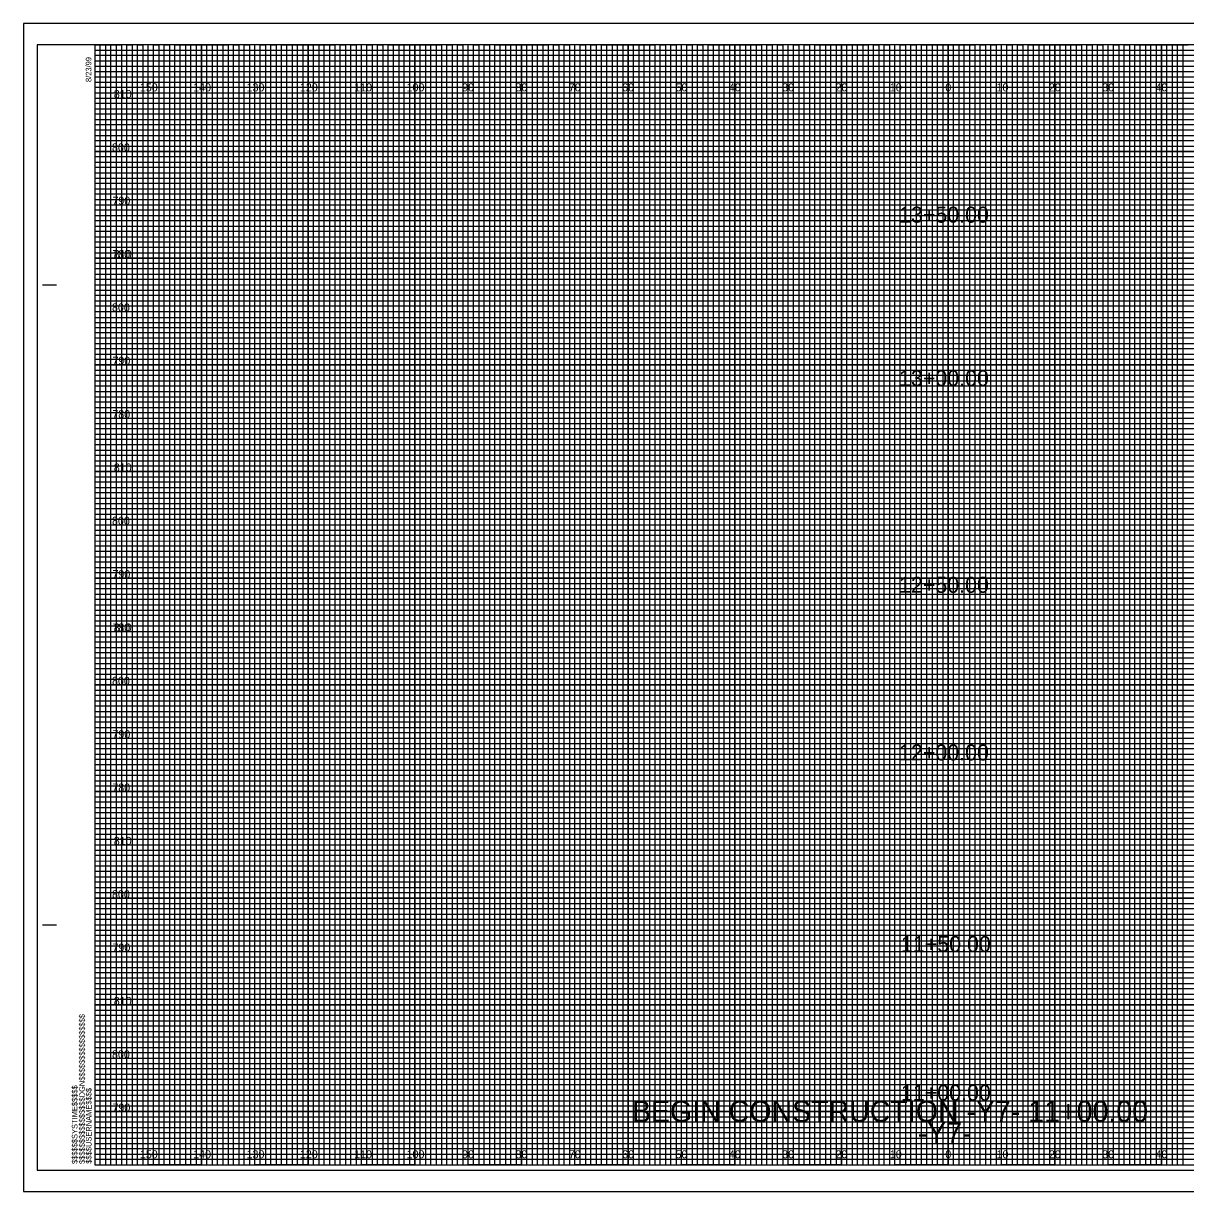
# Model space of a CAD drawing. Extents: x -13 to 323, y -5 to 214.
# Drawn here: x -13.4 to 204.5, y -5 to 214 of the extents above; entities that cross this region are included whole.
import ezdxf

# ---------------------------------------------------------------- set-up
doc = ezdxf.new("R2010")
doc.units = 0
for name, color, linetype in [('Prop XS Alignment Label', 7, 'Continuous'), ('Prop XS Elevation Labels', 7, 'Continuous'), ('Prop XS Offset Labels', 7, 'Continuous'), ('Prop XS Station Labels', 7, 'Continuous'), ('Sheet Cross Section CELL', 7, 'Continuous'), ('Sheet Cross Section Grid Major CELL', 7, 'Continuous'), ('Sheet Cross Section Grid Middle CELL', 7, 'Continuous'), ('Sheet Cross Section Grid Minor 1 CELL', 7, 'Continuous'), ('Sheet Cross Section Grid Minor 2 CELL', 7, 'Continuous'), ('Sheet Cutting Line CELL', 7, 'Continuous'), ('Sheet DOT Grid CELL', 7, 'Continuous'), ('Sheet Plot Border Inside CELL', 7, 'Continuous'), ('Sheet Plot Border Outside CELL', 7, 'Continuous')]:
    doc.layers.add(name, color=color, linetype=linetype)

msp = doc.modelspace()

# ---------------------------------------------------------------- linework, layer by layer
at = {"layer": 'Sheet Cross Section CELL'}
for p, q in [((-9.8, 165), (-7.3, 165)), ((-9.7, 165), (-7.2, 165)), ((-9.8, 45), (-7.3, 45)), ((-9.7, 45), (-7.2, 45)), ((0, 0), (0, 0)), ((0, 0), (0, 0)), ((0, 0), (0, 0)), ((0, 0), (0, 0)), ((0, 0), (0, 0)), ((0, 0), (0, 0)), ((0, 0), (0, 0))]:
    msp.add_line(p, q, dxfattribs=at)
msp.add_lwpolyline([(320, 210), (0, 210), (0, 0), (320, 0)], close=True, dxfattribs=at)
at = {"layer": 'Sheet Cross Section Grid Major CELL'}
for p, q in [((10, 210), (0, 210)), ((10, 0), (10, 210)), ((30, 210), (20, 210)), ((20, 210), (20, 0)), ((30, 0), (30, 210)), ((50, 210), (40, 210)), ((40, 210), (40, 0)), ((50, 0), (50, 210)), ((70, 210), (60, 210)), ((60, 210), (60, 0)), ((70, 0), (70, 210)), ((90, 210), (80, 210)), ((80, 210), (80, 0)), ((90, 0), (90, 210)), ((110, 210), (100, 210)), ((100, 210), (100, 0)), ((110, 0), (110, 210)), ((130, 210), (120, 210)), ((120, 210), (120, 0)), ((130, 0), (130, 210)), ((150, 210), (140, 210)), ((140, 210), (140, 0)), ((150, 0), (150, 210)), ((170, 210), (160, 210)), ((160, 210), (160, 0)), ((170, 0), (170, 210)), ((190, 210), (180, 210)), ((180, 210), (180, 0)), ((190, 0), (190, 210)), ((210, 210), (200, 210)), ((200, 210), (200, 0)), ((20, 0), (10, 0)), ((40, 0), (30, 0)), ((60, 0), (50, 0)), ((80, 0), (70, 0)), ((100, 0), (90, 0)), ((120, 0), (110, 0)), ((140, 0), (130, 0)), ((160, 0), (150, 0)), ((180, 0), (170, 0)), ((200, 0), (190, 0))]:
    msp.add_line(p, q, dxfattribs=at)
for points in [[(0, 200), (320, 200), (320, 190), (0, 190)], [(0, 180), (320, 180), (320, 170), (0, 170)], [(0, 160), (320, 160), (320, 150), (0, 150)], [(0, 140), (320, 140), (320, 130), (0, 130)], [(0, 120), (320, 120), (320, 110), (0, 110)], [(0, 100), (320, 100), (320, 90), (0, 90)], [(0, 80), (320, 80), (320, 70), (0, 70)], [(0, 60), (320, 60), (320, 50), (0, 50)], [(0, 40), (320, 40), (320, 30), (0, 30)], [(0, 20), (320, 20), (320, 10), (0, 10)]]:
    msp.add_lwpolyline(points, dxfattribs=at)
at = {"layer": 'Sheet Cross Section Grid Middle CELL'}
for points in [[(0, 210), (5, 210), (5, 0), (15, 0), (15, 210), (25, 210), (25, 0), (35, 0), (35, 210), (45, 210), (45, 0), (55, 0), (55, 210), (65, 210), (65, 0), (75, 0), (75, 210), (85, 210), (85, 0), (95, 0), (95, 210), (105, 210), (105, 0), (115, 0), (115, 210), (125, 210), (125, 0), (135, 0), (135, 210), (145, 210), (145, 0), (155, 0), (155, 210), (165, 210), (165, 0), (175, 0), (175, 210), (185, 210), (185, 0), (195, 0), (195, 210), (205, 210)], [(0, 205), (275, 205)], [(0, 185), (320, 185), (320, 195), (0, 195)], [(0, 165), (320, 165), (320, 175), (0, 175)], [(0, 145), (320, 145), (320, 155), (0, 155)], [(0, 125), (320, 125), (320, 135), (0, 135)], [(0, 105), (320, 105), (320, 115), (0, 115)], [(0, 85), (320, 85), (320, 95), (0, 95)], [(0, 65), (320, 65), (320, 75), (0, 75)], [(0, 45), (320, 45), (320, 55), (0, 55)], [(0, 25), (320, 25), (320, 35), (0, 35)], [(0, 5), (320, 5), (320, 15), (0, 15)]]:
    msp.add_lwpolyline(points, dxfattribs=at)
at = {"layer": 'Sheet Cross Section Grid Minor 1 CELL'}
for p, q in [((0, 209), (260, 209)), ((260, 207.98), (0, 207.98)), ((0, 207.98), (0, 207)), ((0, 207), (260, 207)), ((260, 205.89), (0, 205.89)), ((0, 205.89), (0, 204)), ((0, 204), (320, 204))]:
    msp.add_line(p, q, dxfattribs=at)
for points in [[(0, 203), (270, 203), (320, 203), (320, 202), (0, 202)], [(0, 201), (320, 201), (320, 199), (0, 199)], [(0, 198), (320, 198), (320, 197), (0, 196.98)], [(0, 196), (320, 196), (320, 194), (0, 194)], [(0, 193), (320, 193), (320, 192), (0, 192)], [(0, 191), (320, 191), (320, 189), (0, 189)], [(0, 188), (320, 188), (320, 187), (0, 187)], [(0, 186), (320, 186), (320, 184), (0, 184)], [(0, 183), (320, 183), (320, 182), (0, 182)], [(0, 181), (320, 181), (320, 179), (0, 179)], [(0, 178), (320, 178), (320, 177), (0, 177)], [(0, 176), (320, 176), (320, 173.95), (320, 173), (320, 172), (0, 172)], [(0, 174), (320, 174), (320, 173), (0, 173)], [(0, 171), (320, 171), (320, 169), (0, 169.03)], [(0, 169.03), (320, 169), (320, 168), (0, 168)], [(0, 167), (320, 167), (320, 166), (0, 166)], [(0, 164), (320, 164), (320, 163), (0, 163)], [(0, 162), (320, 162), (320, 161), (0, 161)], [(-0.07, 158.89), (320, 158.89), (320, 157.88), (-0.07, 157.88)], [(0, 157), (320, 157), (320, 156), (0, 156)], [(0, 154), (320, 154), (320, 153), (0, 153)], [(0, 152), (320, 152), (320, 151), (0, 151)], [(0, 149), (320, 149), (320, 148), (0, 148)], [(0, 147), (320, 147), (320, 146), (0, 146)], [(0, 144), (320, 144), (320, 143), (0, 143)], [(0, 142), (320, 142), (320, 141), (0, 141)], [(0, 139), (320, 139), (319.99, 137.98), (0, 138)], [(0, 137), (320, 137), (320, 136), (0, 136)], [(0, 134), (320, 134), (320, 133), (0, 133)], [(0, 132), (320, 132), (320, 131), (0, 131)], [(0, 129), (320, 129), (320, 128), (0, 128)], [(0, 127), (320, 127), (320, 126), (0, 126)], [(0, 124), (320, 124), (320, 123), (0, 123)], [(0, 122), (320, 122), (320, 121), (0, 121)], [(0, 119), (320, 119), (320, 118), (0, 118)], [(0, 116.99), (320.07, 116.91), (320, 116), (0, 116)], [(0, 114), (320, 114), (320, 113), (0, 113)], [(0, 112), (320, 112), (320, 111), (0, 111)], [(0, 109), (320, 109), (320, 108), (0, 108)], [(0, 107), (320, 107), (320, 106), (0, 106)], [(0, 104), (320, 104), (320, 103), (0, 103)], [(0, 102), (320, 102), (320, 101), (0, 101)], [(0, 99), (320, 99), (320, 98), (0, 98)], [(0, 97), (320, 97), (320, 96), (0, 96)], [(0, 94), (320, 94), (320, 93), (0, 93)], [(0, 92), (320, 92), (320, 91), (0, 91)], [(0, 89), (320, 89), (320, 88), (0, 88)], [(0, 87), (320, 87), (320, 86), (0, 86)], [(0, 84), (320, 84), (320, 83), (0, 83)], [(0, 82), (320, 82), (320, 81), (0, 81)], [(0, 79), (320, 79), (319.99, 77.98), (0, 78)], [(0, 77), (320, 77), (320, 76), (0, 76)], [(0, 74), (320, 74), (320, 73), (0, 73)], [(0, 72), (320, 72), (320, 71), (0, 71)], [(0, 69), (320, 69), (320, 68), (0, 68)], [(0, 67), (320, 67), (320, 66), (0, 66)], [(0, 64), (320, 64), (320, 63), (0, 63)], [(0, 62), (320, 62), (320, 61), (0, 61)], [(0, 59), (320, 59), (320, 58), (0, 58)], [(0, 56.99), (320.07, 56.91), (320, 56), (0, 56)], [(0, 54), (320, 54), (320, 53), (0, 53)], [(0, 52), (320, 52), (320, 51), (0, 51)], [(0, 49), (320, 49), (320, 48), (0, 48)], [(0, 47), (320, 47), (320, 46), (0, 46)], [(0, 44), (320, 44), (320, 43), (0, 43)], [(0, 42), (320, 42), (320, 41), (0, 41)], [(0, 39), (320, 39), (320, 38), (0, 38)], [(0, 37), (320, 37), (320, 36), (0, 36)], [(0, 34), (320, 34), (320, 33), (0, 33)], [(0, 32), (320, 32), (320, 31), (0, 31)], [(0, 29), (320, 29), (320, 28), (0, 28)], [(0, 27), (320, 27), (320, 26), (0, 26)], [(0, 24), (320, 24), (320, 23), (0, 23)], [(0, 22), (320, 22), (320, 21), (0, 21)], [(0, 19), (320, 19), (320, 18), (0, 18)], [(0, 17), (320, 17), (320, 16), (0, 16)], [(0, 14), (320, 14), (320, 13), (0, 13)], [(0, 12), (320, 12), (320, 11), (0, 11)], [(0, 9), (320, 9), (320, 8), (0, 8)], [(0, 7), (320, 7), (320, 6), (0, 6)], [(0, 4), (320, 4), (320, 3), (0, 3)], [(0, 2), (320, 2), (320, 1), (0, 1)]]:
    msp.add_lwpolyline(points, dxfattribs=at)
at = {"layer": 'Sheet Cross Section Grid Minor 2 CELL'}
for points in [[(0, 0), (1, 0), (1, 210), (2, 210), (2, 0)], [(2, 0), (3, 0), (3, 210), (4, 210), (4, 0)], [(5, 0), (6, 0), (6, 210), (7, 210), (7, 0)], [(7, 0), (8, 0), (8, 210), (9, 210), (9, 0)], [(10, 0), (11, 0), (11, 210), (12, 210), (12, 0)], [(12, 0), (13, 0), (13, 210), (14, 210), (14, 0)], [(15, 0), (16, 0), (16, 210), (17, 210), (17, 0)], [(17, 0), (18, 0), (18, 210), (19, 210), (19, 0)], [(20, 0), (21, 0), (21, 210), (22, 210), (22, 0)], [(22, 0), (23, 0), (23, 210), (24, 210), (24, 0)], [(25, 0), (26, 0), (26, 210), (27, 210), (27, 0)], [(27, 0), (28, 0), (28, 210), (29, 210), (29, 0)], [(30, 0), (31, 0), (31, 210), (32, 210), (32, 0)], [(32, 0), (33, 0), (33, 210), (34, 210), (34, 0)], [(35, 0), (36, 0), (36, 210), (37, 210), (37, 0)], [(37, 0), (38, 0), (38, 210), (39, 210), (39, 0)], [(40, 0), (41, 0), (41, 210), (42, 210), (42, 0)], [(42, 0), (43, 0), (43, 210), (44, 210), (44, 0)], [(45, 0), (46, 0), (46, 210), (47, 210), (47, 0)], [(47, 0), (48, 0), (48, 210), (49, 210), (49, 0)], [(50, 0), (51, 0), (51, 210), (52, 210), (52, 0)], [(52, 0), (53, 0), (53, 210), (54, 210), (54, 0)], [(55, 0), (56, 0), (56, 210), (57, 210), (57, 0)], [(57, 0), (58, 0), (58, 210), (59, 210), (59, 0)], [(60, 0), (61, 0), (61, 210), (62, 210), (62, 0)], [(62, 0), (63, 0), (63, 210), (64, 210), (64, 0)], [(65, 0), (66, 0), (66, 210), (67, 210), (67, 0)], [(67, 0), (68, 0), (68, 210), (69, 210), (69, 0)], [(70, 0), (71, 0), (71, 210), (72, 210), (72, 0)], [(72, 0), (73, 0), (73, 210), (74, 210), (74, 0)], [(75, 0), (76, 0), (76, 210), (77, 210), (77, 0)], [(77, 0), (78, 0), (78, 210), (79, 210), (79, 0)], [(80, 0), (81, 0), (81, 210), (82, 210), (82, 0)], [(82, 0), (83, 0), (83, 210), (84, 210), (84, 0)], [(85, 0), (86, 0), (86, 210), (87, 210), (87, 0)], [(87, 0), (88, 0), (88, 210), (89, 210), (89, 0)], [(90, 0), (91, 0), (91, 210), (92, 210), (92, 0)], [(92, 0), (93, 0), (93, 210), (94, 210), (94, 0)], [(95, 0), (96, 0), (96, 210), (97, 210), (97, 0)], [(97, 0), (98, 0), (98, 210), (99, 210), (99, 0)], [(100, 0), (101, 0), (101, 210), (102, 210), (102, 0)], [(102, 0), (103, 0), (103, 210), (104, 210), (104, 0)], [(105, 0), (106, 0), (106, 210), (107, 210), (107, 0)], [(107, 0), (108, 0), (108, 210), (109, 210), (109, 0)], [(110, 0), (111, 0), (111, 210), (112, 210), (112, 0)], [(112, 0), (113, 0), (113, 210), (114, 210), (114, 0)], [(115, 0), (116, 0), (116, 210), (117, 210), (117, 0)], [(117, 0), (118, 0), (118, 210), (119, 210), (119, 0)], [(120, 0), (121, 0), (121, 210), (122, 210), (122, 0)], [(122, 0), (123, 0), (123, 210), (124, 210), (124, 0)], [(125, 0), (126, 0), (126, 210), (127, 210), (127, 0)], [(127, 0), (128, 0), (128, 210), (129, 210), (129, 0)], [(130, 0), (131, 0), (131, 210), (132, 210), (132, 0)], [(132, 0), (133, 0), (133, 210), (134, 210), (134, 0)], [(135, 0), (136, 0), (136, 210), (137, 210), (137, 0)], [(137, 0), (138, 0), (138, 210), (139, 210), (139, 0)], [(140, 0), (141, 0), (141, 210), (142, 210), (142, 0)], [(142, 0), (143, 0), (143, 210), (144, 210), (144, 0)], [(145, 0), (146, 0), (146, 210), (147, 210), (147, 0)], [(147, 0), (148, 0), (148, 210), (149, 210), (149, 0)], [(150, 0), (151, 0), (151, 210), (152, 210), (152, 0)], [(152, 0), (153, 0), (153, 210), (154, 210), (154, 0)], [(155, 0), (156, 0), (156, 210), (157, 210), (157, 0)], [(157, 0), (158, 0), (158, 210), (159, 210), (159, 0)], [(160, 0), (161, 0), (161, 210), (162, 210), (162, 0)], [(162, 0), (163, 0), (163, 210), (164, 210), (164, 0)], [(165, 0), (166, 0), (166, 210), (167, 210), (167, 0)], [(167, 0), (168, 0), (168, 210), (169, 210), (169, 0)], [(170, 0), (171, 0), (171, 210), (172, 210), (172, 0)], [(172, 0), (173, 0), (173, 210), (174, 210), (174, 0)], [(175, 0), (176, 0), (176, 210), (177, 210), (177, 0)], [(177, 0), (178, 0), (178, 210), (179, 210), (179, 0)], [(180, 0), (181, 0), (181, 210), (182, 210), (182, 0)], [(182, 0), (183, 0), (183, 210), (184, 210), (184, 0)], [(185, 0), (186, 0), (186, 210), (187, 210), (187, 0)], [(187, 0), (188, 0), (188, 210), (189, 210), (189, 0)], [(190, 0), (191, 0), (191, 210), (192, 210), (192, 0)], [(192, 0), (193, 0), (193, 210), (194, 210), (194, 0)], [(195, 0), (196, 0), (196, 210), (197, 210), (197, 0)], [(197, 0), (198, 0), (198, 210), (199, 210), (199, 0)], [(200, 0), (201, 0), (201, 210), (202, 210), (202, 0)], [(202, 0), (203, 0), (203, 210), (204, 210), (204, 0)]]:
    msp.add_lwpolyline(points, dxfattribs=at)
at = {"layer": 'Sheet Cutting Line CELL'}
for p, q in [((323.3, 214), (-13.4, 214)), ((-13.4, 214), (-13.4, -5)), ((-13.4, -5), (323.3, -5))]:
    msp.add_line(p, q, dxfattribs=at)
at = {"layer": 'Sheet DOT Grid CELL'}
for p, q in [((10, 0), (10, 210)), ((20, 0), (20, 210)), ((30, 0), (30, 210)), ((40, 0), (40, 210)), ((50, 0), (50, 210)), ((60, 0), (60, 210)), ((70, 0), (70, 210)), ((80, 0), (80, 210)), ((90, 0), (90, 210)), ((100, 0), (100, 210)), ((110, 0), (110, 210)), ((120, 0), (120, 210)), ((130, 0), (130, 210)), ((140, 0), (140, 210)), ((150, 0), (150, 210)), ((160, 0), (160, 210)), ((170, 0), (170, 210)), ((180, 0), (180, 210)), ((190, 0), (190, 210)), ((200, 0), (200, 210)), ((0, 200), (320, 200)), ((0, 190), (320, 190)), ((0, 180), (320, 180)), ((0, 170), (320, 170)), ((0, 160), (320, 160)), ((0, 150), (320, 150)), ((0, 140), (320, 140)), ((0, 130), (320, 130)), ((0, 120), (320, 120)), ((0, 110), (320, 110)), ((0, 100), (320, 100)), ((0, 90), (320, 90)), ((0, 80), (320, 80)), ((0, 70), (320, 70)), ((0, 60), (320, 60)), ((0, 50), (320, 50)), ((0, 40), (320, 40)), ((0, 30), (320, 30)), ((0, 20), (320, 20)), ((0, 10), (320, 10))]:
    msp.add_line(p, q, dxfattribs=at)
at = {"layer": 'Sheet Plot Border Inside CELL'}
msp.add_lwpolyline([(-10.8, -1), (322.4, -1), (322.4, 210), (-10.8, 210)], close=True, dxfattribs=at)
at = {"layer": 'Sheet Plot Border Outside CELL'}
msp.add_lwpolyline([(-13.4, -5), (323.3, -5), (323.3, 214), (-13.4, 214)], close=True, dxfattribs=at)

# ---------------------------------------------------------------- texts
at = {"layer": 'Prop XS Alignment Label'}
for s, p in [('BEGIN CONSTRUCTION -Y7- 11+00.00', (100.7, 8.06)), ('-Y7-', (154.25, 4))]:
    msp.add_text(s, height=4, dxfattribs=at).set_placement(p)
at = {"layer": 'Prop XS Elevation Labels'}
for s, p in [('810', (3.55, 200)), ('800', (3.22, 190)), ('790', (3.3, 180)), ('780', (3.28, 170)), ('810', (3.55, 170)), ('800', (3.22, 160)), ('790', (3.3, 150)), ('780', (3.28, 140)), ('810', (3.55, 130)), ('800', (3.22, 120)), ('790', (3.3, 110)), ('780', (3.28, 100)), ('810', (3.55, 100)), ('800', (3.22, 90)), ('790', (3.3, 80)), ('780', (3.28, 70)), ('810', (3.55, 60)), ('800', (3.22, 50)), ('790', (3.3, 40)), ('810', (3.55, 30)), ('800', (3.22, 20)), ('790', (3.3, 10))]:
    msp.add_text(s, height=1.5, dxfattribs=at).set_placement(p)
at = {"layer": 'Prop XS Offset Labels'}
for s, p in [('150', (8.44, 201.25)), ('140', (18.44, 201.25)), ('130', (28.44, 201.25)), ('120', (38.44, 201.25)), ('110', (48.62, 201.25)), ('100', (58.44, 201.25)), ('90', (68.86, 201.25)), ('80', (78.86, 201.25)), ('70', (88.86, 201.25)), ('60', (98.86, 201.25)), ('50', (108.86, 201.25)), ('40', (118.86, 201.25)), ('30', (128.86, 201.25)), ('20', (138.86, 201.25)), ('10', (149.04, 201.25)), ('0', (159.45, 201.25)), ('0', (159.45, 201.25)), ('10', (169.04, 201.25)), ('20', (178.86, 201.25)), ('30', (188.86, 201.25)), ('40', (198.86, 201.25)), ('150', (8.44, 1.25)), ('140', (18.44, 1.25)), ('130', (28.44, 1.25)), ('120', (38.44, 1.25)), ('110', (48.62, 1.25)), ('100', (58.44, 1.25)), ('90', (68.86, 1.25)), ('80', (78.86, 1.25)), ('70', (88.86, 1.25)), ('60', (98.86, 1.25)), ('50', (108.86, 1.25)), ('40', (118.86, 1.25)), ('30', (128.86, 1.25)), ('20', (138.86, 1.25)), ('10', (149.04, 1.25)), ('0', (159.45, 1.25)), ('0', (159.45, 1.25)), ('10', (169.04, 1.25)), ('20', (178.86, 1.25)), ('30', (188.86, 1.25)), ('40', (198.86, 1.25))]:
    msp.add_text(s, height=1.5, dxfattribs=at).set_placement(p)
at = {"layer": 'Prop XS Station Labels'}
for s, p in [('13+50.00', (150.77, 176.64)), ('13+00.00', (150.77, 146)), ('12+50.00', (150.77, 107.25)), ('12+00.00', (150.77, 75.83)), ('11+50.00', (151.13, 39.91)), ('11+00.00', (151.13, 12.05))]:
    msp.add_text(s, height=3, dxfattribs=at).set_placement(p)
at = {"layer": 'Sheet Cross Section CELL'}
for s, p in [('8/23/99', (-0.65, 203)), ('$$$$$$$$$$$$$$$$DGN$$$$$$$$$$$$$$$$', (-1.88, 0.18)), ('$$$$$$SYSTIME$$$$$', (-3.26, 0.18)), ('$$$$USERNAME$$$$', (-0.62, 0.23))]:
    msp.add_text(s, height=1.05, rotation=90, dxfattribs=at).set_placement(p)

doc.saveas('drawing.dxf')
